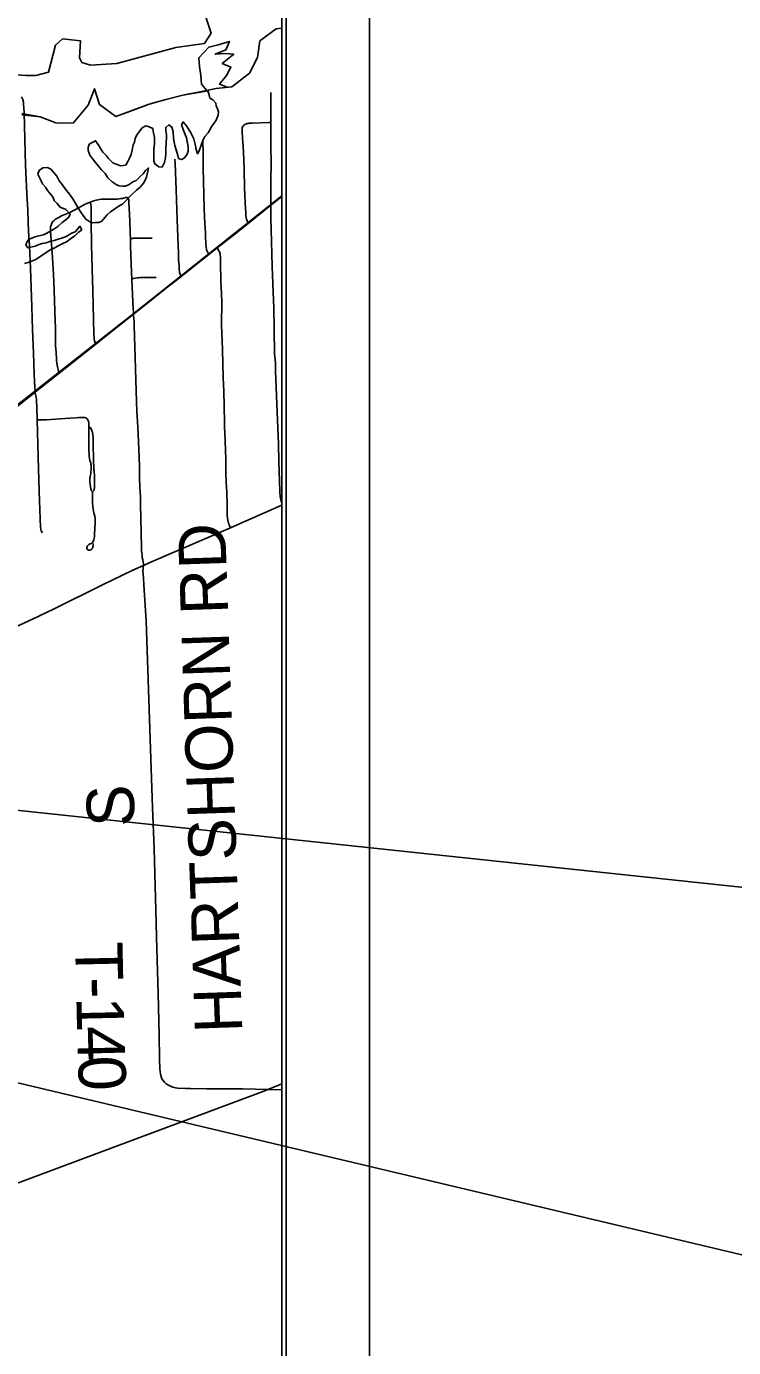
# Model space of a CAD drawing. Extents: x 63.4 to 97.4, y 0.4 to 22.4.
# Drawn here: x 72.001 to 72.849, y 16.734 to 18.319 of the extents above; entities that cross this region are included whole.
import ezdxf

# ---------------------------------------------------------------- set-up
doc = ezdxf.new("R2010")
doc.units = 0
for name, color, linetype in [('GM_X_County_Road', 7, 'Continuous'), ('GM_X_Major_Lake', 7, 'Continuous'), ('GM_X_Minor_River', 7, 'Continuous'), ('GM_X_Rail_Line', 7, 'Continuous'), ('GM_X_State_Route', 7, 'Continuous'), ('GM_X_Township_Road', 7, 'Continuous'), ('GM_X_Township_Road_Text', 7, 'Continuous'), ('SH_Cut_Line', 7, 'Continuous'), ('SH_Data', 7, 'Continuous')]:
    doc.layers.add(name, color=color, linetype=linetype)

msp = doc.modelspace()

# ---------------------------------------------------------------- linework, layer by layer
at = {"layer": 'GM_X_County_Road'}
for points in [[(72.3072, 15.6515), (72.3072, 18.3786)], [(72.2117, 18.3437), (72.2224, 18.3112), (72.2144, 18.2986), (72.18, 18.294), (72.1093, 18.2747), (72.0779, 18.2728), (72.0674, 18.276), (72.0644, 18.2814), (72.0658, 18.3018), (72.0443, 18.3042), (72.036, 18.2967), (72.0274, 18.2642), (72.0123, 18.2602), (72.0008, 18.2604), (71.9392, 18.2647), (71.8765, 18.2621), (71.8141, 18.269), (71.7791, 18.269), (71.7238, 18.2709), (71.6741, 18.2844), (71.6556, 18.2852), (71.6174, 18.2844), (71.5379, 18.3327)]]:
    msp.add_lwpolyline(points, dxfattribs=at)
at = {"layer": 'GM_X_Major_Lake'}
msp.add_lwpolyline([(71.9954, 18.2147), (72.0174, 18.2106), (72.0364, 18.2037), (72.0569, 18.2033), (72.0751, 18.2246), (72.0827, 18.2444), (72.0884, 18.2254), (72.1081, 18.2113), (72.129, 18.2189), (72.148, 18.2258), (72.1681, 18.2315), (72.1886, 18.2368), (72.209, 18.2406), (72.2284, 18.2448), (72.2474, 18.2467), (72.2683, 18.263), (72.2781, 18.282), (72.2808, 18.3018), (72.3005, 18.3162), (72.3072, 18.317)], dxfattribs=at)
at = {"layer": 'GM_X_Minor_River'}
for points in [[(72.2196, 18.2397), (72.211, 18.25), (72.2102, 18.2602), (72.2085, 18.2713), (72.2076, 18.2816), (72.2196, 18.2944), (72.2307, 18.297), (72.2444, 18.3013), (72.2401, 18.291), (72.2273, 18.2859), (72.2393, 18.2867), (72.2495, 18.2859), (72.2358, 18.2748), (72.2461, 18.2705), (72.241, 18.2602), (72.2324, 18.25), (72.2418, 18.2465)], [(72.2187, 18.2418), (72.1886, 18.2368), (72.1681, 18.2315), (72.148, 18.2258), (72.1081, 18.2113), (72.0884, 18.2254), (72.0827, 18.2444), (72.0751, 18.2246), (72.0569, 18.2033), (72.0364, 18.2037), (72.0174, 18.2106), (71.9955, 18.2133)], [(72.2279, 18.2273), (72.2244, 18.2311), (72.221, 18.2333), (72.2202, 18.2371), (72.2185, 18.2425)], [(72.2279, 18.2273), (72.2244, 18.2311), (72.221, 18.2333), (72.2202, 18.2371), (72.2187, 18.2418)], [(72.1466, 18.1452), (72.1474, 18.1494), (72.1436, 18.1463), (72.141, 18.1425), (72.1372, 18.1391), (72.1326, 18.1345), (72.1285, 18.1326), (72.1243, 18.1295), (72.1198, 18.1276), (72.116, 18.1276), (72.1118, 18.1279), (72.1084, 18.1294), (72.1038, 18.1328), (72.0985, 18.1377), (72.0954, 18.1427), (72.0908, 18.1472), (72.087, 18.1521), (72.0839, 18.1559), (72.0805, 18.1601), (72.0771, 18.1646), (72.0751, 18.1703), (72.0751, 18.1745), (72.0766, 18.1783), (72.0804, 18.1802), (72.0838, 18.1821), (72.0876, 18.1765), (72.0899, 18.1727), (72.0926, 18.1685), (72.0968, 18.164), (72.0995, 18.1606), (72.1044, 18.1556), (72.1086, 18.1541), (72.1136, 18.1519), (72.12, 18.1527), (72.1227, 18.1572), (72.1245, 18.1611), (72.1264, 18.1656), (72.1279, 18.1706), (72.129, 18.177), (72.1305, 18.1805), (72.1313, 18.1846), (72.1328, 18.1885), (72.1358, 18.1923), (72.1399, 18.1976), (72.1441, 18.1999), (72.1483, 18.1988), (72.1525, 18.1969), (72.1529, 18.1935), (72.1544, 18.1859), (72.1544, 18.1783), (72.1537, 18.1722), (72.1538, 18.1661), (72.1538, 18.1619), (72.1538, 18.1578), (72.155, 18.1543), (72.1599, 18.1506), (72.1637, 18.1502), (72.1667, 18.1559), (72.1678, 18.1616), (72.1682, 18.1666), (72.1681, 18.1723), (72.1685, 18.1799), (72.1688, 18.1852), (72.1688, 18.1894), (72.168, 18.1939), (72.168, 18.1981), (72.1718, 18.2012), (72.1752, 18.1985), (72.1768, 18.1928), (72.1772, 18.1849), (72.1788, 18.1765), (72.1803, 18.1712), (72.1826, 18.1644), (72.1834, 18.1609), (72.1872, 18.1594), (72.1906, 18.1617), (72.1936, 18.1659), (72.1947, 18.1697), (72.1947, 18.1747), (72.1928, 18.1857), (72.1889, 18.1956), (72.187, 18.2012), (72.1889, 18.2047), (72.1927, 18.1998), (72.198, 18.1914), (72.2015, 18.1842), (72.2034, 18.1778), (72.2046, 18.1717), (72.2061, 18.1664), (72.208, 18.1698), (72.2103, 18.1766), (72.2125, 18.1824), (72.2148, 18.1873), (72.2189, 18.1915), (72.2227, 18.1988), (72.2283, 18.2068), (72.231, 18.2129), (72.2313, 18.2167), (72.2302, 18.2205), (72.2286, 18.2239), (72.2279, 18.2273)], [(71.9988, 18.0347), (72.0044, 18.0362), (72.0124, 18.0397), (72.0211, 18.0454), (72.0302, 18.0515), (72.0336, 18.0527), (72.0381, 18.0554), (72.0446, 18.0588), (72.0499, 18.0611), (72.0544, 18.0646), (72.0586, 18.0676), (72.0631, 18.0718), (72.0673, 18.0753), (72.065, 18.0794), (72.0623, 18.076), (72.0593, 18.0726), (72.0551, 18.071), (72.0514, 18.0687), (72.0479, 18.0668), (72.043, 18.0653), (72.0392, 18.0641), (72.0343, 18.0622), (72.029, 18.061), (72.0248, 18.0595), (72.0199, 18.0587), (72.015, 18.0572), (72.0116, 18.0556), (72.0062, 18.0545), (72.0028, 18.0537), (72.0002, 18.0571), (72.0013, 18.0605), (72.0039, 18.0639), (72.0073, 18.0651), (72.0111, 18.0666), (72.016, 18.0678), (72.0214, 18.0693), (72.0248, 18.0709), (72.0339, 18.0759), (72.0388, 18.0793), (72.0437, 18.0839), (72.0486, 18.0877), (72.052, 18.0904), (72.0535, 18.0938), (72.0482, 18.0995), (72.0413, 18.1025), (72.0379, 18.1067), (72.0344, 18.1105), (72.0329, 18.1139), (72.0302, 18.1177), (72.0264, 18.1222), (72.0237, 18.1264), (72.0203, 18.1305), (72.0188, 18.134), (72.0165, 18.1381), (72.0145, 18.1419), (72.0164, 18.1465), (72.0206, 18.1495), (72.0263, 18.15), (72.0301, 18.1481), (72.0331, 18.1447), (72.0373, 18.1394), (72.0404, 18.1341), (72.0438, 18.1295), (72.0473, 18.1242), (72.0526, 18.1181), (72.0564, 18.1125), (72.0595, 18.1075), (72.0626, 18.1018), (72.066, 18.0965), (72.0691, 18.0924), (72.0721, 18.0878), (72.0759, 18.0856), (72.0801, 18.0837), (72.0839, 18.0841), (72.0877, 18.0841), (72.0915, 18.0856), (72.0949, 18.0898), (72.0979, 18.0933), (72.1017, 18.0967), (72.107, 18.1005), (72.1123, 18.104), (72.1161, 18.1059), (72.1199, 18.1097), (72.1229, 18.1131), (72.127, 18.1173), (72.1331, 18.1227), (72.1372, 18.1265), (72.1418, 18.1315), (72.1448, 18.1383), (72.1466, 18.1452)]]:
    msp.add_lwpolyline(points, dxfattribs=at)
at = {"layer": 'GM_X_Rail_Line'}
for points in [[(65.5072, 16.0914), (66.1191, 16.083), (66.4239, 16.0787), (66.8313, 16.0688), (67.543, 16.0626), (67.9702, 16.0577), (68.6101, 16.2463), (69.1053, 16.3972), (70.1929, 16.7393), (70.2646, 16.7591), (70.3642, 16.7634), (70.5898, 16.7764), (70.6857, 16.8302), (70.7827, 16.8988), (71.2174, 17.2501), (71.5086, 17.4876), (71.6576, 17.6039), (72.13, 17.975), (72.3072, 18.116)], [(70.4785, 16.7566), (71.288, 16.7798), (71.5045, 16.7835), (71.5849, 16.788), (71.6525, 16.8044), (71.7597, 16.8453), (72.2856, 17.0418), (72.3072, 17.0506)]]:
    msp.add_lwpolyline(points, dxfattribs=at)
at = {"layer": 'GM_X_State_Route'}
msp.add_lwpolyline([(71.983, 17.5965), (72.0084, 17.608), (72.0336, 17.6201), (72.092, 17.6492), (72.1285, 17.6667), (72.1413, 17.6725), (72.1483, 17.6756), (72.2455, 17.7178), (72.2538, 17.7214), (72.3072, 17.7447)], dxfattribs=at)
at = {"layer": 'GM_X_Township_Road'}
for p, q in [((72.2667, 18.0827), (72.2941, 18.1046)), ((72.2941, 18.1046), (72.3072, 18.115)), ((72.2197, 18.0455), (72.2297, 18.0534))]:
    msp.add_line(p, q, dxfattribs=at)
for points in [[(72.0025, 18.0987), (72.0015, 18.1184), (71.9999, 18.1529), (71.9983, 18.2157), (71.9979, 18.2217), (71.9975, 18.2251), (71.9973, 18.2277), (71.9969, 18.2303), (71.9965, 18.2316), (71.9958, 18.2333), (71.9949, 18.2349)], [(72.2941, 18.2038), (72.294, 18.2154), (72.294, 18.24)], [(72.2667, 18.0827), (72.2656, 18.0859), (72.2649, 18.0881), (72.2644, 18.0905), (72.2641, 18.0924), (72.2639, 18.096), (72.2634, 18.1068), (72.2628, 18.1172), (72.2624, 18.1254), (72.2619, 18.1469), (72.2615, 18.1594), (72.2608, 18.1753), (72.2605, 18.1805), (72.2602, 18.1842), (72.26, 18.1875), (72.2597, 18.1906), (72.2596, 18.1937), (72.2595, 18.1956), (72.2595, 18.1965), (72.2596, 18.1973), (72.2598, 18.1979), (72.2601, 18.1987)], [(72.2601, 18.1987), (72.2604, 18.1992), (72.2609, 18.1998), (72.2614, 18.2003), (72.2621, 18.2008), (72.2629, 18.2014), (72.2639, 18.2019), (72.2647, 18.2023), (72.2658, 18.2027), (72.2667, 18.2029), (72.2679, 18.2031), (72.2692, 18.2031), (72.2719, 18.2033), (72.2916, 18.2038), (72.2941, 18.2038)], [(72.2941, 18.1046), (72.294, 18.1137), (72.294, 18.1393), (72.2944, 18.1509), (72.2941, 18.1787), (72.2941, 18.2038)], [(72.2197, 18.0455), (72.2186, 18.0478), (72.2176, 18.0496), (72.217, 18.0512), (72.2167, 18.0525), (72.2165, 18.0541), (72.2163, 18.0559), (72.2162, 18.0576), (72.216, 18.0611), (72.2158, 18.0646), (72.2156, 18.0708), (72.2145, 18.0899), (72.2139, 18.1016), (72.2128, 18.149), (72.2128, 18.1597), (72.2127, 18.1693), (72.2125, 18.1796), (72.2125, 18.1833)], [(72.1861, 18.0188), (72.1851, 18.0219), (72.1845, 18.0238), (72.1843, 18.0254), (72.184, 18.0273), (72.1839, 18.0318), (72.1834, 18.0395), (72.1832, 18.048), (72.1828, 18.0563), (72.1815, 18.087), (72.1804, 18.1231), (72.1796, 18.1445), (72.1791, 18.1553), (72.1788, 18.1601)], [(72.0401, 17.903), (72.0394, 17.9055), (72.0389, 17.9074), (72.0385, 17.9092), (72.0378, 17.9128), (72.0374, 17.9154), (72.0372, 17.9179), (72.037, 17.9205), (72.0365, 17.928), (72.0359, 17.9365), (72.0358, 17.9587), (72.0356, 17.9646), (72.0346, 17.9906), (72.0338, 18.013), (72.0331, 18.0289), (72.032, 18.0476), (72.0302, 18.0681), (72.0298, 18.0733), (72.0297, 18.0764), (72.0299, 18.0787), (72.0305, 18.0809), (72.0315, 18.0831), (72.0328, 18.085), (72.0337, 18.0861), (72.0349, 18.0872), (72.0357, 18.0878), (72.0373, 18.0887), (72.0398, 18.0901), (72.0431, 18.0918), (72.0469, 18.0935), (72.053, 18.0961), (72.0641, 18.1021), (72.0679, 18.1041), (72.0715, 18.1058), (72.0774, 18.1083)], [(72.0774, 18.1083), (72.0819, 18.11), (72.0845, 18.1108), (72.0866, 18.1113), (72.0885, 18.1116), (72.0904, 18.1118), (72.0941, 18.1119), (72.1098, 18.1121), (72.112, 18.1123), (72.114, 18.1126), (72.1162, 18.1129), (72.1175, 18.1133), (72.1188, 18.1137), (72.1196, 18.1138), (72.1203, 18.114), (72.1211, 18.114), (72.1219, 18.1138), (72.1226, 18.1134)], [(72.0843, 17.9381), (72.0835, 17.9401), (72.0827, 17.942), (72.0823, 17.944), (72.082, 17.9462), (72.0818, 17.9498), (72.0807, 18.0022), (72.0796, 18.0284), (72.0791, 18.0572), (72.0784, 18.0852), (72.0786, 18.0994), (72.0786, 18.1019), (72.0785, 18.1032), (72.0783, 18.1046), (72.0782, 18.1054), (72.0774, 18.1083)], [(72.1256, 18.0645), (72.1253, 18.0718), (72.1249, 18.0855), (72.1244, 18.0934), (72.1237, 18.1082), (72.1237, 18.1098), (72.1236, 18.1108), (72.1234, 18.1121), (72.123, 18.1128), (72.1226, 18.1134)], [(72.3072, 17.7474), (72.3072, 17.7476), (72.3065, 17.7495), (72.306, 17.7512), (72.3056, 17.7531), (72.3052, 17.7557), (72.305, 17.7572), (72.3049, 17.7588), (72.3048, 17.7622), (72.3035, 17.797), (72.303, 17.8188), (72.3019, 17.8469), (72.2997, 17.906), (72.2994, 17.9144), (72.299, 17.92), (72.2985, 17.9258), (72.2978, 17.9559), (72.2974, 17.9816), (72.2963, 18.0099), (72.2958, 18.0222), (72.2955, 18.0301), (72.295, 18.0476), (72.2946, 18.0602), (72.2942, 18.0757), (72.2941, 18.0895), (72.294, 18.1008), (72.2941, 18.1046)], [(72.0116, 17.8804), (72.0111, 17.8885), (72.0109, 17.8893), (72.0108, 17.8904), (72.0106, 17.8938), (72.0103, 17.9015), (72.0095, 17.9276), (72.0083, 17.9554), (72.0074, 17.9827), (72.0057, 18.0288), (72.0047, 18.0561), (72.0036, 18.0737), (72.0031, 18.0845), (72.0025, 18.0987)], [(72.2297, 18.0534), (72.2509, 18.0701), (72.2667, 18.0827)], [(72.1256, 18.0645), (72.1273, 18.0647), (72.1284, 18.0648), (72.1293, 18.065), (72.1304, 18.065), (72.1314, 18.0651), (72.1324, 18.0651), (72.1415, 18.065), (72.1518, 18.065)], [(72.1274, 18.0161), (72.1271, 18.0242), (72.1259, 18.0551), (72.1256, 18.0645)], [(72.1861, 18.0188), (72.2045, 18.0335), (72.2197, 18.0455)], [(72.2455, 17.7178), (72.2443, 17.7206), (72.2438, 17.7219), (72.2432, 17.7236), (72.2428, 17.725), (72.2424, 17.7268), (72.242, 17.729), (72.2417, 17.7328), (72.2415, 17.7438), (72.2411, 17.761), (72.241, 17.7658), (72.2406, 17.7737), (72.2402, 17.7824), (72.2399, 17.8), (72.2387, 17.8325), (72.2384, 17.8377), (72.2384, 17.8446), (72.2376, 17.8821), (72.2369, 17.8975), (72.2359, 17.9314), (72.2349, 17.961), (72.2347, 17.9695), (72.2354, 17.9805), (72.2352, 17.9888), (72.2347, 17.9984), (72.2339, 18.013), (72.2337, 18.0363), (72.2337, 18.0392), (72.2336, 18.0428), (72.2334, 18.0446), (72.2331, 18.0462), (72.2323, 18.0486), (72.2315, 18.0501), (72.2297, 18.0534)], [(72.1274, 18.0161), (72.1294, 18.0166), (72.1315, 18.0171), (72.1336, 18.0175), (72.1354, 18.0177), (72.1374, 18.0178), (72.1564, 18.0181)], [(72.1295, 17.9739), (72.1289, 17.9835), (72.1286, 17.9854), (72.1284, 17.9892), (72.1277, 18.0062), (72.1274, 18.0161)], [(72.1295, 17.9739), (72.1387, 17.9812), (72.1726, 18.0082), (72.1861, 18.0188)], [(72.0843, 17.9381), (72.1046, 17.9543), (72.1295, 17.9739)], [(72.1413, 17.6725), (72.1413, 17.6744), (72.141, 17.6767), (72.1406, 17.6792), (72.1399, 17.6821), (72.1396, 17.6847), (72.1393, 17.6874), (72.1391, 17.6899), (72.139, 17.6942), (72.1379, 17.7459), (72.1376, 17.7544), (72.1371, 17.7666), (72.1367, 17.7779), (72.1364, 17.7944), (72.1362, 17.799), (72.136, 17.8027), (72.1344, 17.8388), (72.1335, 17.8573), (72.1329, 17.8691), (72.132, 17.8953), (72.1309, 17.9349), (72.1303, 17.9598), (72.13, 17.9643), (72.1296, 17.969), (72.1295, 17.9713), (72.1295, 17.9722), (72.1295, 17.9731), (72.1295, 17.9739)], [(72.0401, 17.903), (72.0803, 17.9349), (72.0843, 17.9381)], [(72.0116, 17.8804), (72.0193, 17.8866), (72.0401, 17.903)], [(71.9704, 17.8477), (72.0013, 17.8722), (72.0116, 17.8804)], [(72.0137, 17.8472), (72.0135, 17.8621), (72.0132, 17.8701), (72.0129, 17.8725), (72.0122, 17.8757), (72.0116, 17.8791), (72.0116, 17.8804)], [(72.0137, 17.8472), (72.0159, 17.847), (72.0251, 17.8473), (72.0529, 17.8493), (72.0604, 17.8497), (72.0636, 17.8499), (72.066, 17.85), (72.0693, 17.85), (72.0704, 17.8499), (72.0717, 17.8496), (72.0729, 17.849), (72.0738, 17.8482)], [(72.0202, 17.7116), (72.0193, 17.7128), (72.0187, 17.7142), (72.0182, 17.7158), (72.0178, 17.7179), (72.0167, 17.7501), (72.0154, 17.7879), (72.0137, 17.8472)], [(72.0759, 17.8397), (72.0759, 17.842), (72.0758, 17.8431), (72.0756, 17.8441), (72.0754, 17.8453), (72.075, 17.8462), (72.0745, 17.8472), (72.0738, 17.8482)], [(72.0801, 17.7609), (72.0792, 17.7618), (72.0787, 17.7625), (72.0784, 17.7634), (72.0781, 17.7642), (72.0776, 17.767), (72.0772, 17.7704), (72.077, 17.7724), (72.0769, 17.7743), (72.0769, 17.7757), (72.0769, 17.7772), (72.0772, 17.7793), (72.0777, 17.7809), (72.078, 17.7834), (72.0784, 17.7898), (72.0784, 17.7928), (72.0782, 17.7941), (72.078, 17.7956), (72.0775, 17.7971), (72.0771, 17.7986), (72.0766, 17.8003), (72.0764, 17.8018), (72.0762, 17.8033), (72.0758, 17.812), (72.0757, 17.8279), (72.0759, 17.8339), (72.0759, 17.8397)], [(72.0801, 17.7609), (72.081, 17.7617), (72.0816, 17.7625), (72.082, 17.7634), (72.0823, 17.7645), (72.0824, 17.7657), (72.0825, 17.7678), (72.0825, 17.7713), (72.0825, 17.7754), (72.0826, 17.7795), (72.0825, 17.7807), (72.0825, 17.7815), (72.0824, 17.7822), (72.0823, 17.7837), (72.0821, 17.785), (72.082, 17.7856), (72.0818, 17.7869), (72.0817, 17.7883), (72.0816, 17.7898), (72.0815, 17.798), (72.081, 17.8197), (72.0808, 17.8247), (72.0804, 17.83), (72.0802, 17.8314), (72.08, 17.8325), (72.0795, 17.834), (72.079, 17.8354), (72.0784, 17.8364), (72.0777, 17.8375), (72.0769, 17.8386), (72.0759, 17.8397)], [(72.0808, 17.699), (72.081, 17.6973), (72.081, 17.6959), (72.0807, 17.6948), (72.0804, 17.6938), (72.08, 17.6931), (72.0794, 17.6923), (72.0788, 17.6917), (72.078, 17.6911), (72.0765, 17.6908), (72.0752, 17.691), (72.0742, 17.6915), (72.0736, 17.6922), (72.0733, 17.6931), (72.0733, 17.694), (72.0736, 17.6951), (72.0741, 17.696), (72.0749, 17.6969), (72.0758, 17.6976), (72.0764, 17.6979), (72.0775, 17.6984), (72.0786, 17.699), (72.0798, 17.6998), (72.0805, 17.7005), (72.081, 17.7013), (72.0815, 17.7025), (72.0818, 17.7037), (72.0821, 17.7051), (72.0824, 17.7067), (72.0826, 17.7086), (72.0827, 17.7109), (72.0831, 17.7161), (72.0833, 17.7243), (72.0832, 17.7289), (72.0828, 17.7317), (72.0823, 17.7341), (72.0813, 17.7375), (72.0808, 17.7405), (72.0805, 17.7433), (72.0802, 17.748), (72.08, 17.7519), (72.08, 17.7563), (72.0801, 17.7609)], [(72.1566, 17.2436), (72.154, 17.3324), (72.1522, 17.3822), (72.1505, 17.4288), (72.1467, 17.5471), (72.1444, 17.6061), (72.1419, 17.6493), (72.1412, 17.6574), (72.1408, 17.6621), (72.1407, 17.6656), (72.1409, 17.6692), (72.1413, 17.6725)], [(72.1664, 17.0525), (72.1648, 17.0545), (72.1635, 17.0566), (72.1624, 17.0593), (72.1617, 17.0622), (72.1611, 17.0683), (72.1606, 17.0807), (72.1601, 17.1087), (72.1591, 17.159), (72.1571, 17.2266), (72.1566, 17.2436)], [(72.1977, 17.0448), (72.1917, 17.0449), (72.1825, 17.0454), (72.1795, 17.0458), (72.1766, 17.0465), (72.1738, 17.0475), (72.1711, 17.0489), (72.1686, 17.0505), (72.1664, 17.0525)], [(72.3072, 17.0434), (72.2602, 17.0444), (72.2166, 17.0446), (72.1977, 17.0448)]]:
    msp.add_lwpolyline(points, dxfattribs=at)
at = {"layer": 'SH_Cut_Line'}
for points in [[(72.3072, 15.6515), (72.3072, 18.3786)], [(72.2117, 18.3437), (72.2224, 18.3112), (72.2144, 18.2986), (72.18, 18.294), (72.1093, 18.2747), (72.0779, 18.2728), (72.0674, 18.276), (72.0644, 18.2814), (72.0658, 18.3018), (72.0443, 18.3042), (72.036, 18.2967), (72.0274, 18.2642), (72.0123, 18.2602), (72.0008, 18.2604), (71.9392, 18.2647), (71.8765, 18.2621), (71.8141, 18.269), (71.7791, 18.269), (71.7238, 18.2709), (71.6741, 18.2844), (71.6556, 18.2852), (71.6174, 18.2844), (71.5379, 18.3327)]]:
    msp.add_lwpolyline(points, dxfattribs=at)
at = {"layer": 'SH_Data'}
for p, q in [((72.4123, 21.4197), (72.4123, 14.4197)), ((72.3123, 21.3197), (72.3123, 14.5197))]:
    msp.add_line(p, q, dxfattribs=at)
msp.add_lwpolyline([(69.5016, 17.6434), (73.2341, 16.7563), (73.2341, 17.2463)], close=True, dxfattribs=at)

# ---------------------------------------------------------------- texts
at = {"layer": 'GM_X_Township_Road_Text'}
for s, height, rotation, p in [('HARTSHORN RD', 0.056818, 91.9446, (72.2599, 17.1124)), ('S', 0.0568, 91.2447, (72.1306, 17.3594)), ('T', 0.0568, 271.2344, (72.0593, 17.2203)), ('-', 0.0568, 271.2521, (72.0603, 17.1778)), ('1', 0.0568, 271.2742, (72.0608, 17.1544)), ('4', 0.0568, 271.4746, (72.0616, 17.1192)), ('0', 0.0568, 272.6114, (72.0625, 17.083))]:
    msp.add_text(s, height=height, rotation=rotation, dxfattribs=at).set_placement(p)

doc.saveas('drawing.dxf')
